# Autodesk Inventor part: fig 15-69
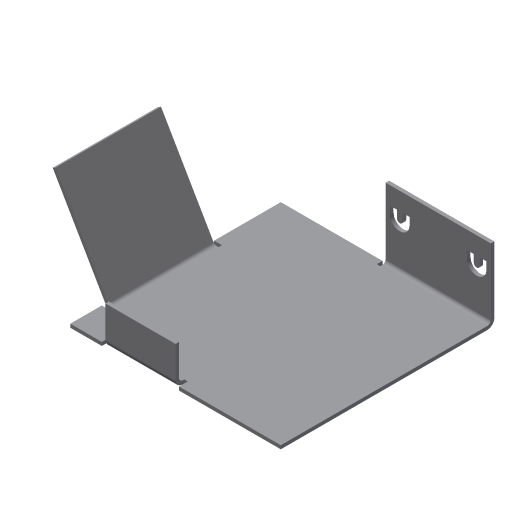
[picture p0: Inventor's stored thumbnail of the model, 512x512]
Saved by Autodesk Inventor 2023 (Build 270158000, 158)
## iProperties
Created: 2002-04
Part Number: fig 15-69
Document SubType Name: Sheet Metal
Density: 1 g/cm^3
Sheet Metal Rule: Default
Material: Generic
Appearance: Default
Control State: 0
Master: False
Checked Out: False
Shininess: 77.0
Angle Display Precision: 2
Document Length Units: 11269
Document Angle Units: 11279
Document Time Units: 11290
Document Mass Units: 11283
Document Length Units Precision: 3
Document Angle Units Precision: 2
Density: 0.0
Volumn: 0.0
Area: 0.0
PropertySet Name: Model Information
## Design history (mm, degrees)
node "Face1"
  sketch "Sketch1"
    geometry: L1 (12.647, 25.882)-(12.647, -14.118); L2 (12.647, -14.118)-(-17.353, -14.118); L3 (-17.353, -14.118)-(-17.353, 15.882); L4 (-17.353, 15.882)-(-2.353, 15.882); L5 (-2.353, 15.882)-(-2.353, 25.882); L6 (-2.353, 25.882)-(12.647, 25.882); 1 further point
    constraints: 12 end point, 4 parallel, 1 perpendicular
    dimensions: "d5" = 30 distance of L2.end L3.end; "d6" = 10 distance of L4.end L5.end; "d7" = 15 distance of L3.end L4.end; "d25" = 15 distance of L5.end L1.start
sketch "Sketch3"
  geometry: L1 (10, -15)-(10, 0)
  constraints: 2 end point
feature "Fold3" sketch "Sketch3" dims "d26" = 0.5 (= BendRadius), "d27" = 90 deg, "d28" = 0.5 (= BendRadius), "d96" = 0.5 (= BendReliefWidth), "d97" = 0.25 (= BendReliefDepth), "d98" = 1 (= MinimumRemnant), "d107" = 0.5 (= Thickness), "SeamGap" = 0.01
node "Flange2"
sketch "Sketch6"
  geometry: L1 (-6.914, 3.413)-(-5.843, 3.413); L2 (-5.843, 0.624)-(-6.914, 0.624); L3 (-6.914, 2.432)-(-5.843, 2.432); L4 (-5.843, 1.605)-(-6.914, 1.605); L5 (-6.914, 0.624)-(-6.914, 1.605); L6 (-6.914, 2.432)-(-6.914, 3.413); L7 (-6.914, 12.568)-(-6.914, 11.587); L8 (-6.914, 14.376)-(-6.914, 13.395); L9 (-6.914, 11.587)-(-5.843, 11.587); L10 (-5.843, 14.376)-(-6.914, 14.376); L11 (-6.914, 12.568)-(-5.843, 12.568); L12 (-5.843, 13.395)-(-6.914, 13.395); A1 r 1.394 centre (-5.843, 2.018) between (-5.843, 0.624) and (-5.843, 3.413); A2 r 0.413 centre (-5.843, 2.018) between (-5.843, 1.605) and (-5.843, 2.432); A3 r 1.394 centre (-5.843, 12.982) between (-5.843, 11.587) and (-5.843, 14.376); A4 r 0.413 centre (-5.843, 12.982) between (-5.843, 12.568) and (-5.843, 13.395)
  constraints: 24 end point, 8 point on circle, 4 centre point, 3 equal length, 1 perpendicular
cut "Cut1" sketch "Sketch6" dims "d49" = 0.5 (= Thickness), "d50" = 0
node "Flange3"
body "Solid1"
face "Plate1" dims "d107" = 0.5 (= Thickness)
sketch "Sketch5"
  geometry: L1 (20, 0)-(5, 0); L2 (5, 0)-(5, 15); L3 (5, 15)-(20, 15); L4 (20, 15)-(20, 0)
  constraints: 8 end point
face "Plate6" dims "d35" = 10, "d36" = 5, "d38" = 15, "d39" = 60 deg, "d40" = 0.5 (= BendRadius), "d107" = 0.5 (= Thickness), "MinimumRemnant" = 1 (= 2 x Thickness), "BendReliefWidth" = 0.5 (= Thickness)
bend "Bend5" dims "d38" = 15, "d39" = 60 deg, "d40" = 0.5 (= BendRadius), "d99" = 0.5 (= BendReliefWidth), "d100" = 0.25 (= BendReliefDepth), "d101" = 1 (= MinimumRemnant), "d107" = 0.5 (= Thickness), "SeamGap" = 0.01, "MinimumRemnant" = 1 (= 2 x Thickness), "BendReliefWidth" = 0.5 (= Thickness), "TransitionRadius" = 0.5 (= BendRadius)
sketch "Sketch7"
  geometry: L1 (25, 0)-(15, 0); L2 (15, 0)-(15, 5); L3 (15, 5)-(25, 5); L4 (25, 5)-(25, 0)
  constraints: 8 end point
face "Plate7" dims "d57" = 5, "d58" = 10, "d60" = 5, "d61" = 90 deg, "d62" = 0.5 (= BendRadius), "d107" = 0.5 (= Thickness), "MinimumRemnant" = 1 (= 2 x Thickness), "BendReliefWidth" = 0.5 (= Thickness)
bend "Bend7" dims "d59" = 0.5 (= BendRadius), "d60" = 5, "d61" = 90 deg, "d62" = 0.5 (= BendRadius), "d102" = 0.5 (= BendReliefWidth), "d103" = 0.25 (= BendReliefDepth), "d104" = 1 (= MinimumRemnant), "d107" = 0.5 (= Thickness), "SeamGap" = 0.01, "MinimumRemnant" = 1 (= 2 x Thickness), "BendReliefWidth" = 0.5 (= Thickness)
other parameters: "Thickness" = 0.5, "BendRadius" = 0.5 (= Thickness), "BendReliefDepth" = 0.25 (= 0.5 x Thickness), "CornerReliefSize" = 2 (= 4 x Thickness), "d0" = 0.5 (= BendRadius), "d13" = 0.5 (= BendRadius), "d31" = 0.5 (= BendRadius), "d37" = 0.5 (= BendRadius), "JacobiRadiusSize" = 0.5 (= Thickness), "GapSize" = 0.5 (= Thickness)
